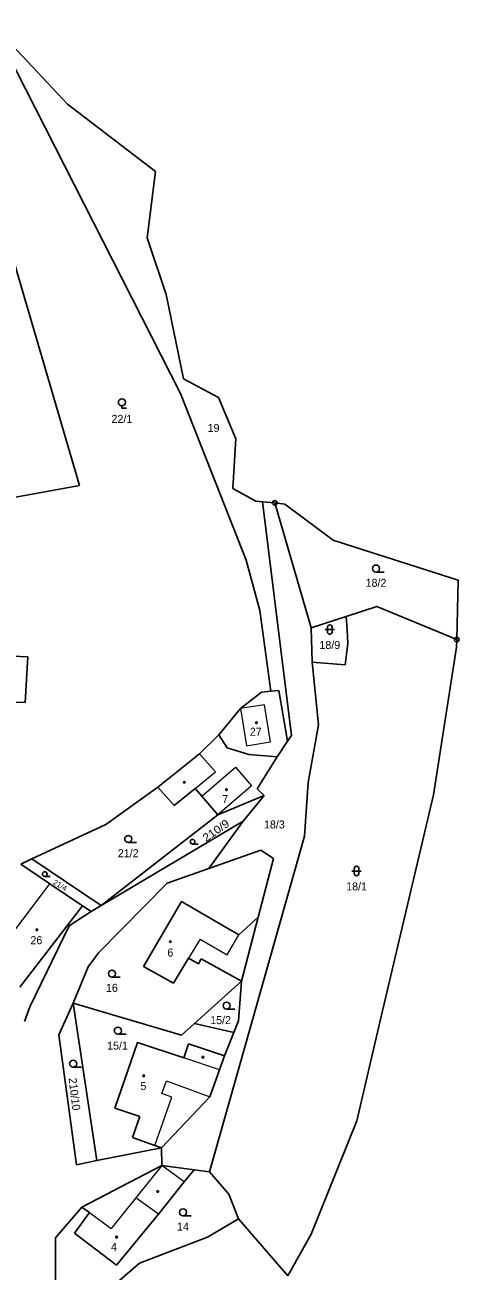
# Model space of a CAD drawing. Extents: x -601877 to -599786, y -1122905 to -1121218.
# Drawn here: x -599878.3 to -599786, y -1122237.3 to -1121972.5 of the extents above; entities that cross this region are included whole.
import ezdxf
from ezdxf.enums import TextEntityAlignment as Align

# ---------------------------------------------------------------- set-up
doc = ezdxf.new("R2010")
doc.units = 0
doc.header["$LTSCALE"] = 0.68
for name, color, linetype, lineweight in [('1', 7, 'Continuous', 25), ('3', 7, 'Continuous', 25), ('4', 7, 'Continuous', 13), ('5', 7, 'Continuous', 25), ('8', 7, 'Continuous', 25)]:
    doc.layers.add(name, color=color, linetype=linetype, lineweight=lineweight)
doc.layers.add('2', color=7, linetype='Continuous')

msp = doc.modelspace()

# ---------------------------------------------------------------- linework, layer by layer
at = {"layer": '1'}
for p, q in [((-599885.16, -1121972.53), (-599845.29, -1122050.83)), ((-599885.16, -1121972.53), (-599873.56, -1121984.8)), ((-599866.71, -1122070.42), (-599894.76, -1121974.97)), ((-599869.27, -1121989.34), (-599873.56, -1121984.8)), ((-599869.27, -1121989.34), (-599850.6, -1122003.66)), ((-599850.6, -1122003.66), (-599852.35, -1122017.78)), ((-599852.35, -1122017.78), (-599848.3, -1122029.83)), ((-599848.3, -1122029.83), (-599844.61, -1122047.74)), ((-599844.61, -1122047.74), (-599837.18, -1122051.72)), ((-599845.29, -1122050.83), (-599831.33, -1122086.27)), ((-599837.18, -1122051.72), (-599833.46, -1122060.51)), ((-599833.46, -1122060.51), (-599834.1, -1122071)), ((-599883.03, -1122073.39), (-599866.71, -1122070.42)), ((-599834.1, -1122071), (-599829.27, -1122073.69)), ((-599829.27, -1122073.69), (-599827.83, -1122073.84)), ((-599827.83, -1122073.84), (-599821.67, -1122123.49)), ((-599827.83, -1122073.84), (-599825.23, -1122074.1)), ((-599825.23, -1122074.1), (-599817.49, -1122100.65)), ((-599825.23, -1122074.1), (-599823.04, -1122074.33)), ((-599823.04, -1122074.33), (-599812.82, -1122082.03)), ((-599810.16, -1122082.88), (-599812.82, -1122082.03)), ((-599786.25, -1122090.52), (-599810.16, -1122082.88)), ((-599831.33, -1122086.27), (-599828.36, -1122096.95)), ((-599786.52, -1122103.14), (-599786.25, -1122090.52)), ((-599828.36, -1122096.95), (-599826.03, -1122114.11)), ((-599803.5, -1122096.11), (-599810.06, -1122098.24)), ((-599803.5, -1122096.11), (-599786.52, -1122103.14)), ((-599810.06, -1122098.24), (-599817.49, -1122100.65)), ((-599809.83, -1122101.09), (-599810.06, -1122098.24)), ((-599817.49, -1122100.65), (-599817.27, -1122107.97)), ((-599809.68, -1122103.98), (-599809.83, -1122101.09)), ((-599810.21, -1122108.47), (-599809.68, -1122103.98)), ((-599786.55, -1122104.74), (-599791.49, -1122136.14)), ((-599786.55, -1122104.74), (-599786.52, -1122103.14)), ((-599877.73, -1122106.77), (-599880.89, -1122106.69)), ((-599878.28, -1122116.51), (-599877.73, -1122106.77)), ((-599817.27, -1122107.97), (-599810.21, -1122108.47)), ((-599817.27, -1122107.97), (-599815.9, -1122121.22)), ((-599832.53, -1122117.8), (-599828.02, -1122114.32)), ((-599828.02, -1122114.32), (-599826.03, -1122114.11)), ((-599826.03, -1122114.11), (-599824.34, -1122113.94)), ((-599824.34, -1122113.94), (-599822.5, -1122124.74)), ((-599878.28, -1122116.51), (-599887.92, -1122116.14)), ((-599832.53, -1122117.8), (-599837.13, -1122123.36)), ((-599815.9, -1122121.22), (-599818.1, -1122133.49)), ((-599837.13, -1122123.36), (-599841.25, -1122127.38)), ((-599837.13, -1122123.36), (-599835.33, -1122126.15)), ((-599821.67, -1122123.49), (-599822.5, -1122124.74)), ((-599835.33, -1122126.15), (-599830.75, -1122127.58)), ((-599822.5, -1122124.74), (-599824.7, -1122128.04)), ((-599841.25, -1122127.38), (-599850.11, -1122134.51)), ((-599830.75, -1122127.58), (-599824.7, -1122128.04)), ((-599828.93, -1122134.87), (-599824.7, -1122128.04)), ((-599861.11, -1122142.4), (-599850.11, -1122134.51)), ((-599850.11, -1122134.51), (-599846.59, -1122138.41)), ((-599818.1, -1122133.49), (-599818.92, -1122144.88)), ((-599846.59, -1122138.41), (-599842.15, -1122134.78)), ((-599842.15, -1122134.78), (-599840.75, -1122136.42)), ((-599840.75, -1122136.42), (-599837.33, -1122140.4)), ((-599837.33, -1122140.4), (-599827.45, -1122136.24)), ((-599827.45, -1122136.24), (-599831.96, -1122141.69)), ((-599827.45, -1122136.24), (-599828.93, -1122134.87)), ((-599791.49, -1122136.14), (-599797.56, -1122161.91)), ((-599876.84, -1122149.73), (-599861.11, -1122142.4)), ((-599862.11, -1122159.65), (-599837.33, -1122140.4)), ((-599862.11, -1122159.65), (-599831.96, -1122141.69)), ((-599831.96, -1122141.69), (-599839.24, -1122151.77)), ((-599818.92, -1122144.88), (-599839.06, -1122216.21)), ((-599879.23, -1122150.85), (-599876.84, -1122149.73)), ((-599862.11, -1122159.65), (-599876.84, -1122149.73)), ((-599828.15, -1122147.85), (-599839.24, -1122151.77)), ((-599828.76, -1122162.14), (-599825.5, -1122149.68)), ((-599825.5, -1122149.68), (-599828.15, -1122147.85)), ((-599873.01, -1122155.04), (-599879.23, -1122150.85)), ((-599839.24, -1122151.77), (-599848.06, -1122154.89)), ((-599866.09, -1122159.7), (-599873.01, -1122155.04)), ((-599848.06, -1122154.89), (-599862.68, -1122169.7)), ((-599879.44, -1122176.97), (-599866.09, -1122159.7)), ((-599868.91, -1122163.98), (-599864.26, -1122160.93)), ((-599864.26, -1122160.93), (-599866.09, -1122159.7)), ((-599864.26, -1122160.93), (-599862.11, -1122159.65)), ((-599845.02, -1122158.77), (-599853.1, -1122172.57)), ((-599832.87, -1122165.86), (-599845.02, -1122158.77)), ((-599832.87, -1122165.86), (-599828.76, -1122162.14)), ((-599832.32, -1122175.71), (-599828.76, -1122162.14)), ((-599802.86, -1122184.44), (-599797.56, -1122161.91)), ((-599877.31, -1122181.17), (-599868.91, -1122163.98)), ((-599862.68, -1122169.7), (-599864.88, -1122172.67)), ((-599843.53, -1122170.83), (-599846.74, -1122176.16)), ((-599841.44, -1122172.05), (-599843.53, -1122170.83)), ((-599841.44, -1122172.05), (-599840.85, -1122170.98)), ((-599832.32, -1122175.71), (-599840.85, -1122170.98)), ((-599864.88, -1122172.67), (-599868.07, -1122180.41)), ((-599846.74, -1122176.16), (-599853.1, -1122172.57)), ((-599842.26, -1122184.69), (-599832.32, -1122175.71)), ((-599832.32, -1122175.71), (-599832.95, -1122184.17)), ((-599878.41, -1122184.29), (-599877.31, -1122181.17)), ((-599871.15, -1122187.14), (-599868.07, -1122180.41)), ((-599868.07, -1122180.41), (-599845.02, -1122187.18)), ((-599863.05, -1122213.85), (-599868.07, -1122180.41)), ((-599842.26, -1122184.69), (-599845.02, -1122187.18)), ((-599833.92, -1122186.61), (-599832.95, -1122184.17)), ((-599807.77, -1122205.39), (-599802.86, -1122184.44)), ((-599867.4, -1122214.71), (-599871.15, -1122187.14)), ((-599854.37, -1122188.75), (-599859.22, -1122202.69)), ((-599844.56, -1122192.04), (-599854.37, -1122188.75)), ((-599844.56, -1122192.04), (-599843.54, -1122189.01)), ((-599835.89, -1122191.59), (-599843.54, -1122189.01)), ((-599836.98, -1122194.59), (-599835.89, -1122191.59)), ((-599839.05, -1122200.27), (-599836.98, -1122194.59)), ((-599849.33, -1122211.12), (-599839.05, -1122200.27)), ((-599859.22, -1122202.69), (-599853.94, -1122204.46)), ((-599853.94, -1122204.46), (-599855.5, -1122208.94)), ((-599807.77, -1122205.39), (-599817.45, -1122229.46)), ((-599863.05, -1122213.85), (-599849.33, -1122211.12)), ((-599849.33, -1122211.12), (-599849.25, -1122214.9)), ((-599867.4, -1122214.71), (-599863.05, -1122213.85)), ((-599849.25, -1122214.9), (-599866.25, -1122223.72)), ((-599849.25, -1122214.9), (-599842.34, -1122215.79)), ((-599844.46, -1122218.39), (-599842.34, -1122215.79)), ((-599842.34, -1122215.79), (-599839.06, -1122216.21)), ((-599839.06, -1122216.21), (-599834.98, -1122220.99)), ((-599849.96, -1122225.24), (-599844.46, -1122218.39)), ((-599834.98, -1122220.99), (-599832.94, -1122226.2)), ((-599866.25, -1122223.72), (-599871.81, -1122230.28)), ((-599864.64, -1122224.89), (-599866.25, -1122223.72)), ((-599867.82, -1122229.27), (-599864.64, -1122224.89)), ((-599858.85, -1122236.09), (-599849.96, -1122225.24)), ((-599839.55, -1122230.11), (-599832.94, -1122226.2)), ((-599832.94, -1122226.2), (-599822.46, -1122238.34)), ((-599858.85, -1122236.09), (-599867.82, -1122229.27)), ((-599822.46, -1122238.34), (-599817.45, -1122229.46)), ((-599871.81, -1122230.28), (-599871.81, -1122239.72)), ((-599854, -1122235.63), (-599839.55, -1122230.11)), ((-599862.87, -1122243.28), (-599854, -1122235.63))]:
    msp.add_line(p, q, dxfattribs=at)
for points in [[(-599835.89, -1122191.59), (-599833.92, -1122186.61), (-599842.26, -1122184.69)], [(-599855.5, -1122208.94), (-599850.72, -1122210.63), (-599849.33, -1122211.12)]]:
    msp.add_lwpolyline(points, dxfattribs=at)
at = {"layer": '3'}
for p, q in [((-599803.683, -1122088.8), (-599801.933, -1122088.8)), ((-599814.511, -1122101.011), (-599812.509, -1122101.011)), ((-599814.011, -1122100.511), (-599814.011, -1122101.512)), ((-599813.009, -1122101.512), (-599813.009, -1122100.511)), ((-599856.373, -1122146.25), (-599854.623, -1122146.25)), ((-599842.685, -1122146.59), (-599841.513, -1122146.59)), ((-599808.821, -1122152.311), (-599806.819, -1122152.311)), ((-599808.321, -1122151.811), (-599808.321, -1122152.812)), ((-599807.319, -1122152.812), (-599807.319, -1122151.811)), ((-599874.125, -1122153.47), (-599872.953, -1122153.47)), ((-599859.843, -1122174.86), (-599858.093, -1122174.86)), ((-599835.453, -1122181.66), (-599833.703, -1122181.66)), ((-599858.573, -1122187), (-599856.823, -1122187)), ((-599868.083, -1122194.01), (-599866.333, -1122194.01)), ((-599844.733, -1122225.59), (-599842.983, -1122225.59))]:
    msp.add_line(p, q, dxfattribs=at)
msp.add_lwpolyline([(-599857.72, -1122053.472), (-599857.72, -1122053.97), (-599856.719, -1122053.97)], dxfattribs=at)
for centre, radius in [((-599857.7193, -1122052.7209), 0.75), ((-599803.6829, -1122088.0498), 0.75), ((-599856.3729, -1122145.4998), 0.75), ((-599842.6852, -1122146.0874), 0.5025), ((-599874.1252, -1122152.9674), 0.5025), ((-599859.8429, -1122174.1098), 0.75), ((-599835.4529, -1122180.9098), 0.75), ((-599858.5729, -1122186.2498), 0.75), ((-599868.0829, -1122193.2598), 0.75), ((-599844.7329, -1122224.8398), 0.75)]:
    msp.add_circle(centre, radius, dxfattribs=at)
for centre, start, end in [((-599813.51, -1122100.5109), 0, 180), ((-599813.51, -1122101.5109), 180, 359.98789), ((-599807.82, -1122151.8109), 0, 180), ((-599807.82, -1122152.8109), 180, 359.98789)]:
    msp.add_arc(centre, 0.5, start, end, dxfattribs=at)
at = {"layer": '4'}
for p, q in [((-599827.5, -1122116.98), (-599826.22, -1122124.88)), ((-599841.25, -1122127.38), (-599837.83, -1122131.24)), ((-599842.15, -1122134.78), (-599837.83, -1122131.24)), ((-599840.75, -1122136.42), (-599833.56, -1122130.25)), ((-599833.56, -1122130.25), (-599830.14, -1122134.23)), ((-599830.14, -1122134.23), (-599837.33, -1122140.4)), ((-599885.94, -1122172.01), (-599873.01, -1122155.04)), ((-599835.37, -1122170.09), (-599832.87, -1122165.86)), ((-599841.08, -1122166.77), (-599843.53, -1122170.83)), ((-599841.08, -1122166.77), (-599835.37, -1122170.09)), ((-599836.98, -1122194.59), (-599844.56, -1122192.04)), ((-599849.21, -1122199.6), (-599848.24, -1122196.92)), ((-599848.24, -1122196.92), (-599839.05, -1122200.27)), ((-599849.25, -1122214.9), (-599854.75, -1122221.75)), ((-599844.46, -1122218.39), (-599849.25, -1122214.9)), ((-599854.75, -1122221.75), (-599859.99, -1122228.27)), ((-599849.96, -1122225.24), (-599854.75, -1122221.75)), ((-599864.64, -1122224.89), (-599859.99, -1122228.27))]:
    msp.add_line(p, q, dxfattribs=at)
for points in [[(-599827.5, -1122116.98), (-599832.53, -1122117.8), (-599831.25, -1122125.7), (-599826.22, -1122124.88)], [(-599850.72, -1122210.63), (-599847.1, -1122200.37), (-599849.21, -1122199.6)]]:
    msp.add_lwpolyline(points, dxfattribs=at)
at = {"layer": '5'}
for centre in [(-599829.1068, -1122120.7792), (-599844.4468, -1122133.4792), (-599835.4868, -1122135.0292), (-599875.8068, -1122164.7992), (-599847.4268, -1122167.3192), (-599840.4968, -1122191.8692), (-599853.1068, -1122195.8292), (-599850.0968, -1122220.4092), (-599858.8568, -1122230.1092)]:
    msp.add_circle(centre, 0.175, dxfattribs=at)
at = {"layer": '8'}
for centre, radius in [((-599825.23, -1122074.0999), 0.5), ((-599825.23, -1122074.0999), 0.0303), ((-599786.52, -1122103.1399), 0.5), ((-599786.52, -1122103.1399), 0.0303)]:
    msp.add_circle(centre, radius, dxfattribs=at)

# ---------------------------------------------------------------- texts
at = {"layer": '2'}
for s, p in [('22/1', (-599857.719, -1122057.095)), ('19', (-599838.229, -1122059.015)), ('18/2', (-599803.689, -1122091.925)), ('18/9', (-599813.509, -1122105.135)), ('27', (-599829.259, -1122123.565)), ('7', (-599835.75, -1122137.875)), ('18/3', (-599825.299, -1122143.265)), ('21/2', (-599856.379, -1122149.375)), ('18/1', (-599807.819, -1122156.435)), ('26', (-599875.909, -1122167.865)), ('6', (-599847.42, -1122170.485)), ('16', (-599859.849, -1122177.985)), ('15/2', (-599836.739, -1122184.845)), ('15/1', (-599858.659, -1122190.265)), ('5', (-599853.15, -1122198.855)), ('14', (-599844.739, -1122228.715)), ('4', (-599859.41, -1122233.025))]:
    msp.add_text(s, height=1.7, dxfattribs=at).set_placement(p, align=Align.CENTER)
for s, height, rotation, width, p in [('210/9', 1.7, 35, 1.1, (-599837.2375, -1122144.3934)), ('21/4', 1.14, 329, 1.05, (-599871.1666, -1122155.8337))]:
    msp.add_text(s, height=height, rotation=rotation, dxfattribs=dict(at, width=width)).set_placement(p, align=Align.CENTER)
msp.add_text('210/10', height=1.7, rotation=277, dxfattribs=at).set_placement((-599868.6351, -1122199.8139), align=Align.CENTER)

doc.saveas('drawing.dxf')
